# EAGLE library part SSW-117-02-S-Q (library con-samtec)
THROUGH-HOLE .025" SQ POST SOCKET Source: Samtec SSW.pdf
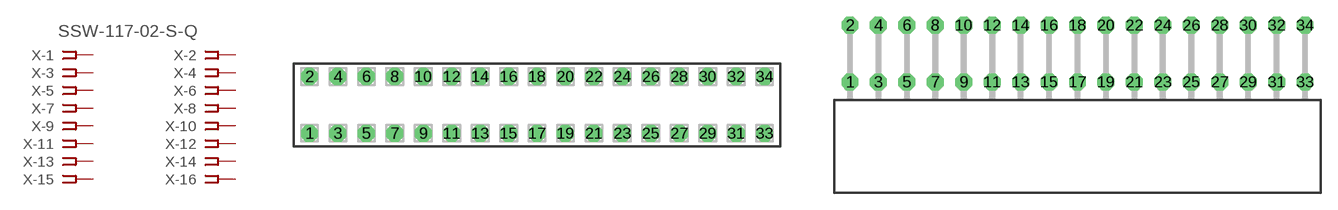
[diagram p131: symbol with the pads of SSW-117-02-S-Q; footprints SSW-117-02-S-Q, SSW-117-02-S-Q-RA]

Designator prefix X; gates -1=FPINV -2=FPIN -3=FPIN -4=FPIN -5=FPIN -6=FPIN -7=FPIN -8=FPIN -9=FPIN -10=FPIN -11=FPIN -12=FPIN -13=FPIN -14=FPIN -15=FPIN -16=FPIN -17=FPIN -18=FPIN -19=FPIN -20=FPIN -21=FPIN -22=FPIN -23=FPIN -24=FPIN -25=FPIN -26=FPIN -27=FPIN -28=FPIN -29=FPIN -30=FPIN -31=FPIN -32=FPIN -33=FPIN -34=FPIN

## SSW-117-02-S-Q (MPN: SSW-117-02-S-Q; OC_FARNELL: unknown; OC_NEWARK: 82P7588)  [SSW-117-02-S-Q]
1  -1:1  pas
2  -2:1  pas
3  -3:1  pas
4  -4:1  pas
5  -5:1  pas
6  -6:1  pas
7  -7:1  pas
8  -8:1  pas
9  -9:1  pas
10  -10:1  pas
11  -11:1  pas
12  -12:1  pas
13  -13:1  pas
14  -14:1  pas
15  -15:1  pas
16  -16:1  pas
17  -17:1  pas
18  -18:1  pas
19  -19:1  pas
20  -20:1  pas
21  -21:1  pas
22  -22:1  pas
23  -23:1  pas
24  -24:1  pas
25  -25:1  pas
26  -26:1  pas
27  -27:1  pas
28  -28:1  pas
29  -29:1  pas
30  -30:1  pas
31  -31:1  pas
32  -32:1  pas
33  -33:1  pas
34  -34:1  pas

## SSW-117-02-S-QRA (OC_FARNELL: unknown; OC_NEWARK: unknown)  [SSW-117-02-S-Q-RA]
Pads as for SSW-117-02-S-Q

## Footprint SSW-117-02-S-Q (pad centres in mm)
THROUGH-HOLE .025" SQ POST SOCKET Source: Samtec SSW.pdf
drill 1 pad 1.5 octagon: 1 -20.32,-2.54; 2 -20.32,2.54; 3 -17.78,-2.54; 4 -17.78,2.54; 5 -15.24,-2.54; 6 -15.24,2.54; 7 -12.7,-2.54; 8 -12.7,2.54; 9 -10.16,-2.54; 10 -10.16,2.54; 11 -7.62,-2.54; 12 -7.62,2.54; 13 -5.08,-2.54; 14 -5.08,2.54; 15 -2.54,-2.54; 16 -2.54,2.54; 17 0,-2.54; 18 0,2.54; 19 2.54,-2.54; 20 2.54,2.54; 21 5.08,-2.54; 22 5.08,2.54; 23 7.62,-2.54; 24 7.62,2.54; 25 10.16,-2.54; 26 10.16,2.54; 27 12.7,-2.54; 28 12.7,2.54; 29 15.24,-2.54; 30 15.24,2.54; 31 17.78,-2.54; 32 17.78,2.54; 33 20.32,-2.54; 34 20.32,2.54

## Footprint SSW-117-02-S-Q-RA (pad centres in mm)
THROUGH-HOLE .025" SQ POST SOCKET Source: Samtec SSW.pdf
drill 1 pad 1.5 octagon: 1 -20.32,1.524; 2 -20.32,6.604; 3 -17.78,1.524; 4 -17.78,6.604; 5 -15.24,1.524; 6 -15.24,6.604; 7 -12.7,1.524; 8 -12.7,6.604; 9 -10.16,1.524; 10 -10.16,6.604; 11 -7.62,1.524; 12 -7.62,6.604; 13 -5.08,1.524; 14 -5.08,6.604; 15 -2.54,1.524; 16 -2.54,6.604; 17 0,1.524; 18 0,6.604; 19 2.54,1.524; 20 2.54,6.604; 21 5.08,1.524; 22 5.08,6.604; 23 7.62,1.524; 24 7.62,6.604; 25 10.16,1.524; 26 10.16,6.604; 27 12.7,1.524; 28 12.7,6.604; 29 15.24,1.524; 30 15.24,6.604; 31 17.78,1.524; 32 17.78,6.604; 33 20.32,1.524; 34 20.32,6.604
